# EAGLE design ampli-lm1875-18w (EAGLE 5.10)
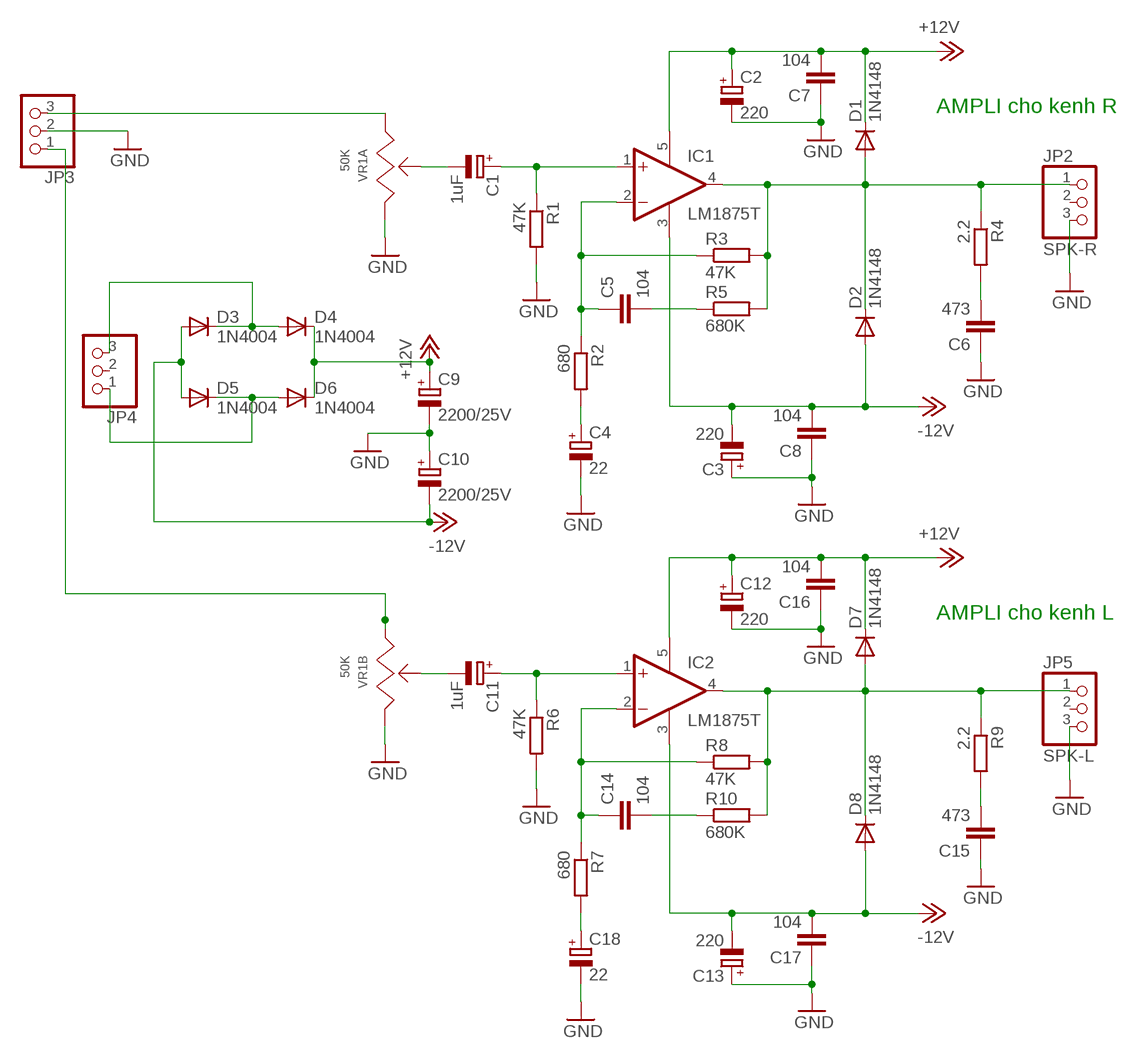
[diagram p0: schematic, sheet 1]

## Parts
C1  1uF  CPOL-EUE2.5-5  [E2,5-5]
C2  220  CPOL-EUTT5D9  [TT5D9]
C3  220  CPOL-EUTT5D9  [TT5D9]
C4  22  CPOL-EUE2.5-6  [E2,5-6]
C5  104  C-EU050-025X075  [C050-025X075]
C6  473  C-EU050-025X075  [C050-025X075]
C7  104  C-EU050-025X075  [C050-025X075]
C8  104  C-EU050-025X075  [C050-025X075]
C9  2200/25V  CPOL-EUE5-10.5  [E5-10,5]
C10  2200/25V  CPOL-EUE5-10.5  [E5-10,5]
C11  1uF  CPOL-EUE2.5-5  [E2,5-5]
C12  220  CPOL-EUTT5D9  [TT5D9]
C13  220  CPOL-EUTT5D9  [TT5D9]
C14  104  C-EU050-025X075  [C050-025X075]
C15  473  C-EU050-025X075  [C050-025X075]
C16  104  C-EU050-025X075  [C050-025X075]
C17  104  C-EU050-025X075  [C050-025X075]
C18  22  CPOL-EUE2.5-6  [E2,5-6]
D1  1N4148  [DO35-10]
D2  1N4148  [DO35-10]
D3  1N4004  [DO41-10]
D4  1N4004  [DO41-10]
D5  1N4004  [DO41-10]
D6  1N4004  [DO41-10]
D7  1N4148  [DO35-10]
D8  1N4148  [DO35-10]
IC1  LM1875T  [CB360]
IC2  LM1875T  [CB360]
JP2  SPK-R  PINHD-1X3  [1X03]
JP3  PINHD-1X3  [1X03]
JP4  PINHD-1X3  [1X03]
JP5  SPK-L  PINHD-1X3  [1X03]
R1  47K  R-EU_0204/7  [0204/7]
R2  680  R-EU_0204/7  [0204/7]
R3  47K  R-EU_0204/7  [0204/7]
R4  2.2  R-EU_0204/7  [0204/7]
R5  680K  R-EU_0204/7  [0204/7]
R6  47K  R-EU_0204/7  [0204/7]
R7  680  R-EU_0204/7  [0204/7]
R8  47K  R-EU_0204/7  [0204/7]
R9  2.2  R-EU_0204/7  [0204/7]
R10  680K  R-EU_0204/7  [0204/7]
VR1  50K  VR VOL  [VR VOL]

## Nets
+12V [70mil]: C2.+ C7.2 C9.+ C12.+ C16.2 D1.C D4.C D6.C D7.C IC1.5(V+) IC2.5(V+)
-12V [20mil]: C3.- C8.2 C10.- C13.- C17.2 D2.A D3.A D5.A D8.A IC1.3(V-) IC2.3(V-)
AC1 [70mil]: D3.C D4.A JP4.3
AC2 [70mil]: D5.C D6.A JP4.1
GND: C2.- C3.+ C4.- C6.1 C7.1 C8.1 C9.- C10.+ C12.- C13.+ C15.1 C16.1 C17.1 C18.- JP2.3 JP3.2 JP5.3 R1.2 R6.2 VR1.103 VR1.203
N$1: C1.+ IC1.1(+IN) R1.1
N$2: C5.1 IC1.2(-IN) R2.1 R3.1
N$3: C4.+ R2.2
N$4 [20mil]: C11.+ IC2.1(+IN) R6.1
N$5: C5.2 R5.1
N$6: C6.2 R4.2
N$7: C1.- VR1.102
N$8 [20mil]: C14.1 IC2.2(-IN) R7.1 R8.1
N$9: C18.+ R7.2
N$10: C14.2 R10.1
N$11: C15.2 R9.2
N$12 [20mil]: C11.- VR1.202
N$13 [20mil]: JP3.1 VR1.201
R-IN [20mil]: JP3.3 VR1.101
SPK-R [70mil]: D1.A D2.C IC1.4(OUT) JP2.1 R3.2 R4.1 R5.2
SPK-R1 [70mil]: D7.A D8.C IC2.4(OUT) JP5.1 R8.2 R9.1 R10.2
Unconnected: JP2.2 JP4.2 JP5.2

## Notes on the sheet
- AMPLI cho kenh R
- AMPLI cho kenh L

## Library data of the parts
C1-C4 C9-C13 C18 = rcl:CPOL-EU: POLARIZED CAPACITOR, European symbol
C5-C8 C14-C17 = rcl:C-EU: CAPACITOR, European symbol
D1 D2 D7 D8 = DIODE:1N4148: DIODE
D3-D6 = DIODE:1N4004: DIODE
IC1 IC2 = linear:LM1875T: Power OP AMP
JP2-JP5 = pinhead:PINHD-1X3: PIN HEADER
R1-R10 = rcl:R-EU_: RESISTOR, European symbol
VR1 = Agnort-Part:VR VOL

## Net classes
0 20_mil: width 0.508 mm
1 70mil: width 1.778 mm
2 20mil: width 0.508 mm

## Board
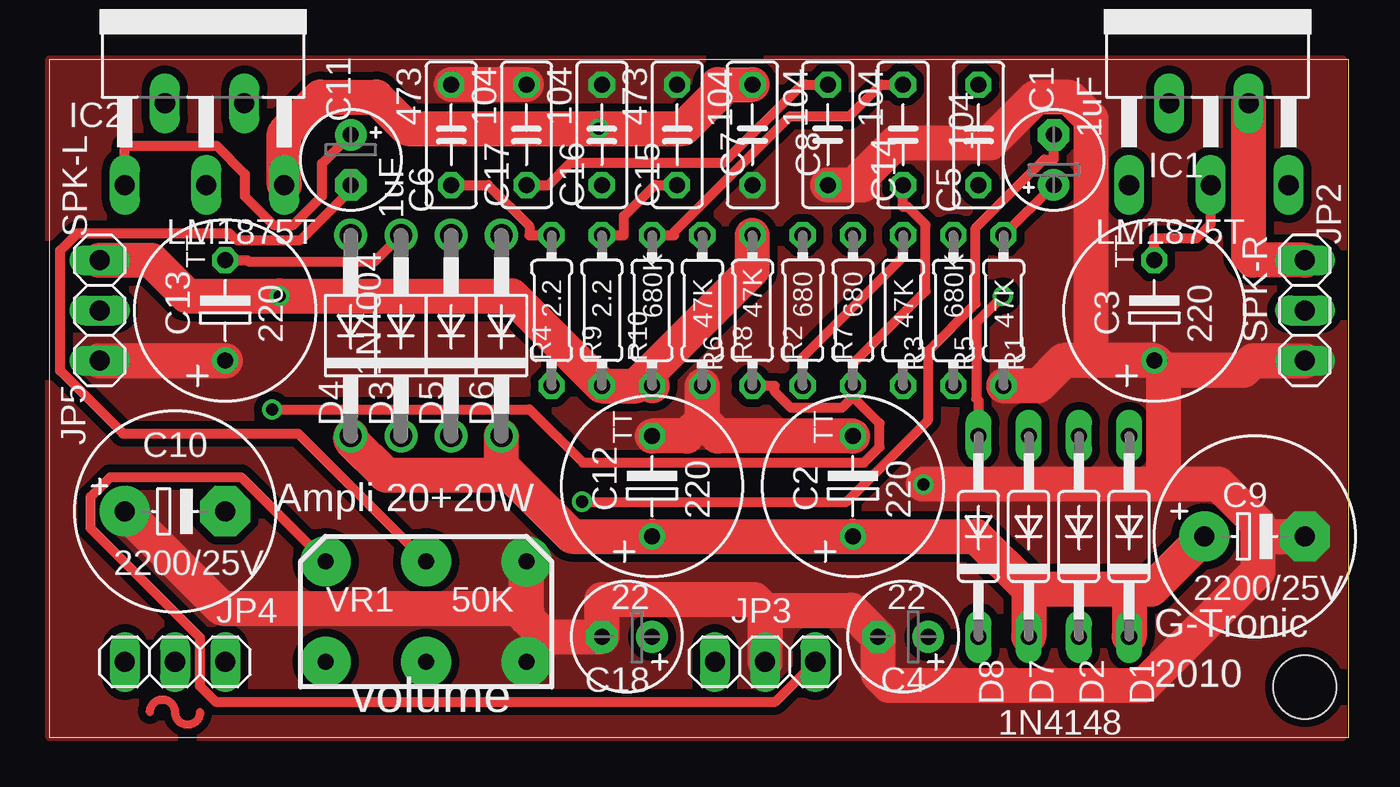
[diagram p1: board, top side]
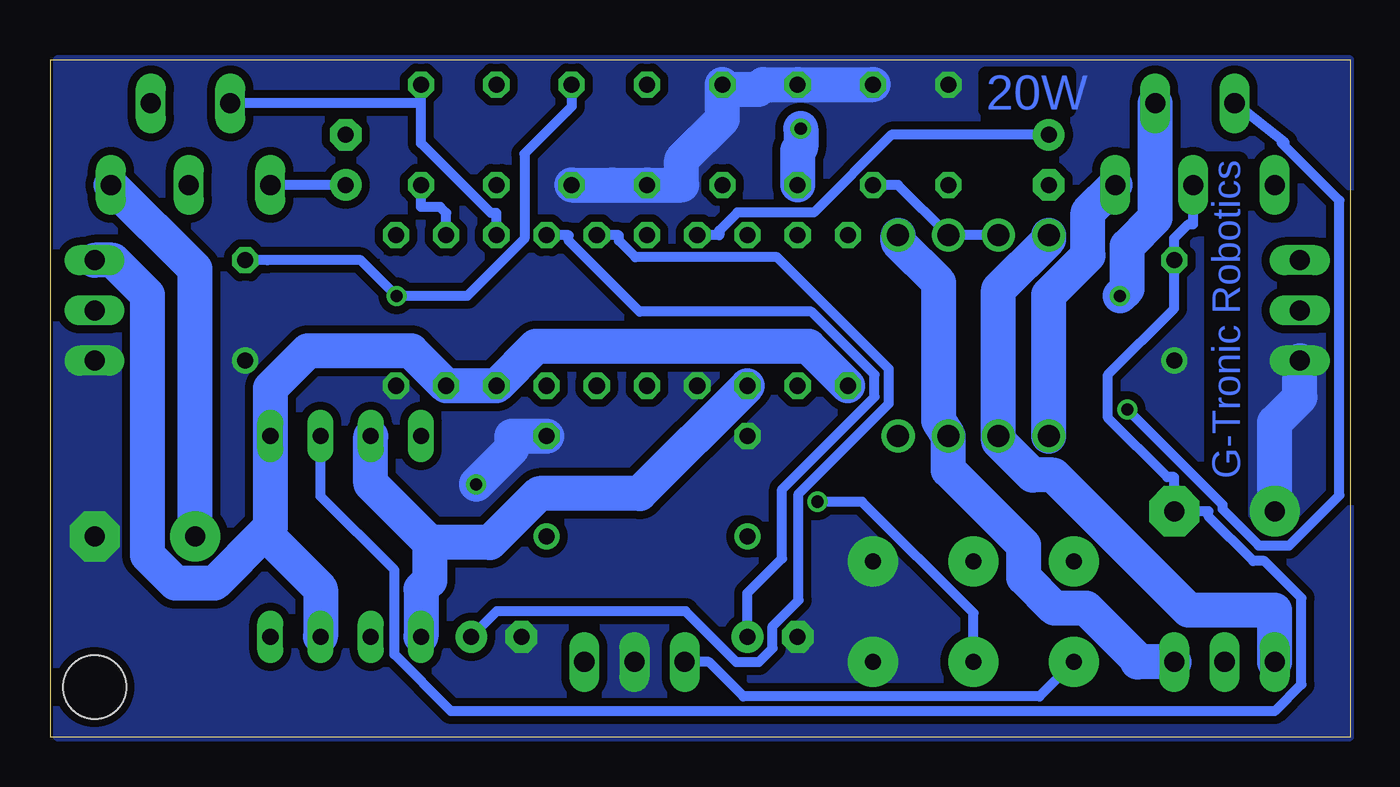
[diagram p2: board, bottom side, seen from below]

Size 65.71 x 34.28 mm. Coordinates in mm from the lower left corner, seen from the top.
Outline: 0,0 65.71,0 65.71,34.28 0,34.28 0,0
Copper layers (1*16): Top 0.035mm / dielectric 1.5mm / Bottom 0.035mm
Design rules "default *": minimum track width 10mil, minimum drill 24mil, track to track 8mil, track to pad 8mil, pad to pad 8mil, via to via 8mil, smd to smd 8mil, copper to edge 0mil, drill to drill 8mil, minimum pad ring 10mil, minimum via ring 8mil, stop-mask expansion 4mil, vias tented up to drill 0mil, thermal gap 10mil
Holes 3.2 mm at 63.5,2.54

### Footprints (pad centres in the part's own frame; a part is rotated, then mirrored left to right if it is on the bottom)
E2,5-5 = drill 0.813 pad 1.6 round: + -1.27,0 | drill 0.813 pad 1.6 octagon: - 1.27,0
TT5D9 = drill 0.813 round: + -2.54,0 | drill 0.813 octagon: - 2.54,0
E2,5-6 = drill 0.813 pad 1.6 round: + -1.27,0 | drill 0.813 pad 1.6 octagon: - 1.27,0
C050-025X075 = drill 0.813 octagon: 1 -2.54,0; 2 2.54,0
E5-10,5 = drill 1.016 pad 2.54 round: + -2.54,0 | drill 1.016 pad 2.54 octagon: - 2.54,0
DO35-10 = drill 0.813 long: A 5.08,0; C -5.08,0
DO41-10 = drill 1.118 round: A 5.08,0; C -5.08,0
CB360 = drill 1.016 long: 1 -3.81,-8.89; 2 -1.778,-4.763; 3 0.318,-8.89; 4 2.235,-4.763; 5 4.255,-8.89
1X03 = drill 1.016 long: 1 -2.54,0; 2 0,0; 3 2.54,0
0204/7 = drill 0.813 octagon: 1 -3.81,0; 2 3.81,0
VR VOL = drill 0.813 pad 2.54 round: 101 -5.08,-2.54; 102 0,-2.54; 103 5.08,-2.54; 201 -5.08,2.54; 202 0,2.54; 203 5.08,2.54

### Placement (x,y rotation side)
C1  50.8,29.21 90 top
C2  40.64,12.7 90 top
C3  55.88,21.59 90 top
C4  43.18,5.08 180 top
C5  46.99,30.48 270 top
C6  20.32,30.48 270 top
C7  35.56,30.48 90 top
C8  39.37,30.48 90 top
C9  60.96,10.16 0 top
C10  6.35,11.43 0 top
C11  15.24,29.21 270 top
C12  30.48,12.7 90 top
C13  8.89,21.59 90 top
C14  43.18,30.48 90 top
C15  31.75,30.48 270 top
C16  27.94,30.48 270 top
C17  24.13,30.48 270 top
C18  29.21,5.08 180 top
D1  54.61,10.16 90 top
D2  52.07,10.16 90 top
D3  17.78,20.32 90 top
D4  15.24,20.32 90 top
D5  20.32,20.32 90 top
D6  22.86,20.32 90 top
D7  49.53,10.16 90 top
D8  46.99,10.16 90 top
IC1  58.42,36.83 0 top
IC2  7.62,36.83 0 top
JP2  63.5,21.59 270 top
JP3  36.2,3.81 180 top
JP4  6.35,3.81 180 top
JP5  2.54,21.59 270 top
R1  48.26,21.59 270 top
R2  38.1,21.59 90 top
R3  43.18,21.59 270 top
R4  25.4,21.59 90 top
R5  45.72,21.59 270 top
R6  33.02,21.59 270 top
R7  40.64,21.59 90 top
R8  35.56,21.59 90 top
R9  27.94,21.59 90 top
R10  30.48,21.59 270 top
VR1  19.05,6.35 0 top

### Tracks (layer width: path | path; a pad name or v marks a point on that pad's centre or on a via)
+12V  (via drill 0.61 pad 1.02)
  Top 1.778: IC2.5 11.87,30.56 13.7,32.38 16.53,32.38 18.12,30.79 v27.78,30.79 32.05,30.79 33.81,32.55 33.81,33.02 C7.2 | 49.53,7.49 54.61,7.49 | 49.53,7.49 46.86,10.16 C2.+ C12.+ 26.42,10.16 22.86,13.72 | 54.61,7.49 54.61,7 D1.C | 22.86,13.72 D6.C | D4.C 15.24,15.05 17.03,13.26 22.4,13.26 22.86,13.72 | C9.+ 55.75,7.49 54.61,7.49 | 49.53,7.49 D7.C
  Bottom 1.778: IC2.5 13.26,26.56 13.26,24.37 15.24,22.39 D4.C | C9.+ 58.42,23.69 IC1.5 | v27.78,30.79 27.78,29.85 27.94,29.69 C16.2
-12V  (via drill 0.61 pad 1.02)
  Top 0.508: C13.- 10.01,24.13 10.06,24.07 16.45,24.07 D3.A | D8.A 46.99,17.02 46.88,17.13 46.88,20.97 v48.23,22.33 | IC1.3 58.74,25.96 58.03,25.25 55.88,25.25 C3.- | C8.2 38.25,33.02 38.05,33.02 34.09,29.06 26.36,29.06 25.25,27.94 C17.2
  Bottom 0.508: IC2.3 7.94,25.96 8.18,25.96 8.89,25.25 C13.- 8.89,21.69 12.24,18.34 12.24,16.15 9.25,13.16 8.89,13.16 C10.- 7.16,11.43 7.16,11.17 4.91,8.91 4.33,8.91 2.46,7.04 2.46,2.67 3.81,1.32 45.48,1.32 48.34,4.18 48.34,8.46 52.07,12.19 D2.A | C8.2 39.37,31.9 41.76,29.52 41.76,25.22 44.65,22.33 v48.23,22.33 50.04,24.13 54.76,24.13 C3.- | D3.A D5.A 22.86,27.94 C17.2
AC1
  Bottom 1.778: D4.A 15.24,25.19 17.78,22.65 D3.C 17.78,14.98 16.06,13.26 15,13.26 8.17,6.43 3.81,6.43 JP4.3
AC2
  Bottom 1.778: JP4.1 10.74,3.81 10.74,3.93 13.35,6.53 14.95,6.53 16.51,8.08 16.51,9.71 20.32,13.52 D5.C 20.8,16 20.8,23 22.86,25.06 D6.A
GND  (via drill 0.61 pad 1.02)
  Top 1.778: JP5.3 C13.+ | JP2.3 60.88,19.05 60.4,18.57 56.36,18.57 | 56.36,12.8 56.36,18.57 | 56.36,18.57 C3.+ 52.69,19.05 | 56.36,12.8 v44.2,12.8 | 61.14,10.16 61.14,10.8 59.14,12.8 56.36,12.8 | 61.14,10.16 61.14,8.4 55.35,2.62 42.48,2.62 41.91,3.19 C4.- 40.56,6.43 36.2,6.43 | 52.69,19.05 51.28,19.05 50.01,17.78 R1.2 | 52.69,19.05 52.69,31.27 51.59,32.38 49.89,32.38 47.58,30.07 42.79,30.07 41.12,28.39 41.12,27.94 C8.1 | 24.13,6.53 8.71,6.53 C10.+ | 24.13,6.53 24.13,6.04 25.09,5.08 | 24.13,6.53 VR1.203 | 25.09,5.08 24.13,4.12 VR1.103 | 25.09,5.08 C18.- 27.94,6.97 35.65,6.97 36.2,6.43 | 36.2,6.43 JP3.2 | 33.02,16.03 33.81,15.24 C2.- | C12.- 32.23,15.24 33.02,16.03 | 33.02,16.03 R6.2 | 61.14,10.16 C9.- | C17.1 C6.1
  Bottom 1.778: JP5.3 2.54,17.2 3.81,15.93 C10.+ | 31.75,32.77 29.94,32.77 29.69,33.02 C16.1 C17.1 | 31.75,32.77 C15.1 | 31.75,32.77 31.75,32.4 31.75,31.27 33.81,29.21 33.81,27.94 C7.1 37.31,27.94 C8.1 | v44.2,12.8 42.39,14.6 42.39,15.24 C2.-
  pour Top (isolate 0.406, no thermals): 0,34.29 65.41,34.29 65.41,0 0,0
  pour Bottom (isolate 0.406, no thermals): 0,34.29 65.41,34.29 65.41,0 0,0
N$1
  Top 0.508: R1.1 C1.+
  Bottom 0.508: C1.+ IC1.1
N$2
  Top 0.508: R3.1 43.18,24.28 38.1,19.2 R2.1
  Bottom 0.508: 46.99,32.07 C5.1 | 46.99,32.07 46.99,30.05 43.46,26.52 43.18,26.52 R3.1 | 46.99,32.07 IC1.2
N$3
  Bottom 0.508: R2.2 36.98,25.4 36.98,25.12 36.14,24.28 28.98,24.28 23.34,18.64 23.34,16.88 27.9,12.32 27.9,6.93 29.21,5.61 29.21,4.51 29.91,3.8 31.04,3.8 33.61,6.37 43.16,6.37 C4.+
N$4
  Top 0.508: IC2.1 3.81,29.92 8.46,29.92 9.89,28.5 9.89,27.37 11.34,25.92 12.34,25.92 13.79,27.37 13.79,29.03 C11.+
  Bottom 0.508: C11.+ 23.19,30.48 27.13,26.54 30.99,26.54 31.9,25.63 31.9,25.4 R6.1
N$5
  Bottom 0.508: C5.2 46.99,26.82 46.02,26.82 45.72,26.52 R5.1
N$6
  Top 0.508: R4.2 24.28,25.4 24.28,25.86 22.2,27.94 C6.2
N$7  (via drill 0.61 pad 1.02)
  Top 0.508: v26.93,11.91 40.31,11.91 44.45,16.06 44.45,19.55 46.84,21.94 46.84,25.76 50.3,29.22 50.8,29.22 C1.-
  Bottom 0.508: VR1.102 19.05,6.28 24.68,11.91 v26.93,11.91
N$8  (via drill 0.61 pad 1.02)
  Top 0.508: 40.64,17.22 41.99,15.87 41.99,14.68 41.2,13.89 26.98,13.89 24.28,16.59 v11.27,16.59 | R8.1 36.68,17.78 36.68,17.5 37.52,16.66 40.08,16.66 40.64,17.22 | 40.64,17.22 R7.1 40.64,18.9 44.31,22.57 44.31,25.92 43.41,26.82 43.18,26.82 C14.1
  Bottom 0.508: v11.27,16.59 6.45,11.76 6.45,11.53 4.62,9.7 3.08,9.7 0.54,12.24 0.54,27.16 3.47,30.09 3.3,30.09 IC2.2
N$9
  Bottom 0.508: R7.2 39.52,25.4 39.52,25.12 35.93,21.53 27.24,21.53 24.05,18.34 24.05,17.22 28.73,12.54 28.73,9.04 30.48,7.3 C18.+
N$10
  Top 0.508: C14.2 42.06,33.02 40.45,31.41 37.45,31.41 31.6,25.56 31.6,25.4 R10.1
N$11
  Top 0.508: C15.2 30.63,27.94 29.06,26.36 29.06,25.4 R9.2
N$12
  Top 0.508: VR1.202 12.58,15.36 3.73,15.36 0.54,18.54 0.54,24.62 1.42,25.5 9.1,25.5 9.45,25.15 12.7,25.15 15.24,27.69 C11.-
N$13
  Top 0.508: VR1.201 9.69,13.17 3.09,13.17 2.08,12.16 2.08,10.57 7.62,5.03 7.62,2.58 8.4,1.8 36.72,1.8 JP3.1
N$14
  Top 0.406: 7.62,1.27 arc-180 6.35,1.27
N$15
  Top 0.406: 5.08,1.27 arc-180 6.35,1.27
R-IN
  Bottom 0.508: JP3.3 32.44,3.81 30.69,2.07 15.71,2.07 VR1.101
SPK-R
  Top 1.778: JP2.1 60.88,24.13 60.65,24.36 IC1.4
  Bottom 1.778: 54.9,10.32 57.44,7.79 59.4,7.79 60.82,9.21 60.82,22.37 62.58,24.13 JP2.1 | 54.9,10.32 54.61,10.61 54.61,12.83 D1.A 54.61,17.65 52.72,19.54 47.48,19.54 R5.2 R3.2 41.19,19.77 27.39,19.77 R4.1 | 54.9,10.32 52.07,7.49 D2.C
SPK-R1  (via drill 0.61 pad 1.02)
  Top 1.778: JP5.1 5.16,24.13 6.96,22.32 v11.64,22.32 23.4,22.32 R9.1 29.69,17.78 30.09,18.17 | 30.09,18.17 35.56,23.65 R8.2 | 30.09,18.17 R10.2
  Bottom 1.778: IC2.4 9.85,26.28 11.28,24.86 11.28,22.68 v11.64,22.32 | D8.C 46.99,7.49 46.55,7.93 46.55,9.85 | 46.55,9.85 49.53,12.83 D7.A | R10.2 35.93,12.33 41.02,12.33 43.5,9.85 46.55,9.85

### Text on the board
Bottom: 20W | G-Tronic Robotics
tNames: Ampli 20+20W | G-Tronic | 2010 | volume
